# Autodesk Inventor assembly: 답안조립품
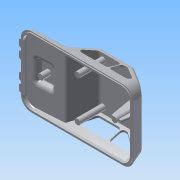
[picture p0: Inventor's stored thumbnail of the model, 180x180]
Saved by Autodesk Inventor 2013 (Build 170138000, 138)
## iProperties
Created: 2015-05
Part Number: 답안조립품
Document SubType Name: Assembly
Designer: Administrator
Author: Administrator
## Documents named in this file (2)
- C:\Documents and Settings\Administrator\바탕 화면\450507V1019\답안조립품.iam
- C:\Documents and Settings\Administrator\바탕 화면\450507V1019\1-본체.ipt
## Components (1 placed, 1 different names)
1. 1-본체:1
